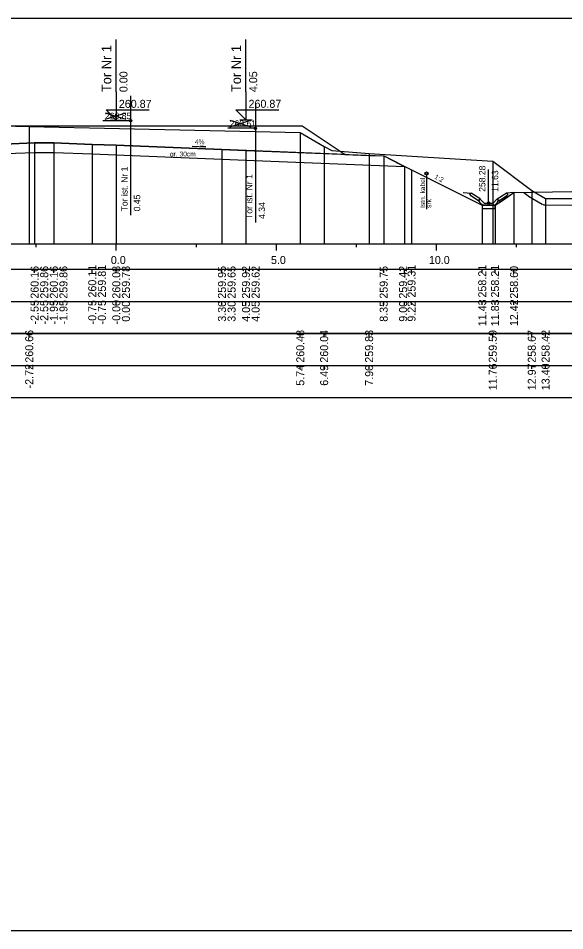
# Model space of a CAD drawing. Extents: x 6516023 to 6560129, y 5513077 to 5529206.
# Drawn here: x 6517307.15 to 6517324.22, y 5514484.66 to 5514513.16 of the extents above; entities that cross this region are included whole.
import ezdxf

# ---------------------------------------------------------------- set-up
doc = ezdxf.new("R2010")
doc.units = 0
for name, color, linetype in [('IR_default', 7, 'Continuous'), ('TOR_PRZEK_P-kable', 7, 'Continuous'), ('TOR_PRZEK_P-komponent', 7, 'Continuous'), ('TOR_PRZEK_P-odwodnienie', 7, 'Continuous'), ('TOR_PRZEK_P-opisy', 7, 'Continuous'), ('TOR_PRZEK_P-tabelka istniejace', 7, 'Continuous'), ('TOR_PRZEK_P-tabelka projektowane', 7, 'Continuous'), ('TOR_PRZEK_P-teren istniejacy', 7, 'Continuous'), ('TOR_PRZEK_P-tory istniejace', 7, 'Continuous'), ('TOR_PRZEK_P-tory projektowane', 7, 'Continuous'), ('TOR_PRZEK_P-uklad odniesienia', 7, 'Continuous'), ('TOR_PRZEK_P-warstwa ochronna I', 7, 'Continuous'), ('TOR_PRZEK_P-warstwa ochronna II', 7, 'Continuous'), ('TOR_PS_T-skarpy projektowane', 7, 'Continuous'), ('TOR_RAMKI-ramka+tabelka 1', 7, 'Continuous')]:
    doc.layers.add(name, color=color, linetype=linetype)

msp = doc.modelspace()

# ---------------------------------------------------------------- linework, layer by layer
at = {"layer": 'IR_default'}
msp.add_lwpolyline([(6517306.097, 5514509.798), (6517307.463, 5514509.798), (6517308.073, 5514509.798), (6517308.463, 5514509.798), (6517310.597, 5514509.798), (6517311.963, 5514509.798), (6517312.298, 5514509.799), (6517312.513, 5514509.799), (6517314.647, 5514509.799), (6517316.013, 5514509.799), (6517316.834, 5514509.252), (6517317.359, 5514508.902), (6517318.093, 5514508.873), (6517318.563, 5514508.854), (6517319.093, 5514508.589), (6517319.433, 5514508.419), (6517320.29, 5514507.99), (6517321.64, 5514507.315), (6517321.796, 5514507.315), (6517322.04, 5514507.315), (6517322.269, 5514507.467), (6517322.632, 5514507.71), (6517325.042, 5514507.758)], dxfattribs=at)
at = {"layer": 'TOR_PRZEK_P-kable'}
msp.add_line((6517319.901, 5514508.307), (6517319.901, 5514507.197), dxfattribs=at)
msp.add_circle((6517319.901, 5514508.307), 0.05, dxfattribs=at)
at = {"layer": 'TOR_PRZEK_P-komponent'}
msp.add_lwpolyline([(6517294.775, 5514509.735), (6517298.211, 5514509.865), (6517299.146, 5514509.242), (6517302.945, 5514509.118), (6517303.963, 5514509.797), (6517307.463, 5514509.798), (6517308.463, 5514509.798), (6517311.963, 5514509.798), (6517312.513, 5514509.799), (6517316.013, 5514509.799), (6517317.359, 5514508.902), (6517313.513, 5514509.056), (6517310.213, 5514509.188), (6517309.463, 5514509.218), (6517308.263, 5514509.266), (6517307.663, 5514509.266), (6517306.463, 5514509.218), (6517305.713, 5514509.188), (6517303.513, 5514509.1), (6517298.792, 5514509.253), (6517297.342, 5514509.195), (6517296.592, 5514509.165), (6517293.75, 5514509.052)], close=True, dxfattribs=at)
at = {"layer": 'TOR_PRZEK_P-odwodnienie'}
for p, q in [((6517321.84, 5514507.385), (6517321.84, 5514508.429)), ((6517321.531, 5514507.444), (6517321.27, 5514507.619)), ((6517321.576, 5514507.511), (6517321.295, 5514507.698)), ((6517321.533, 5514507.48), (6517321.58, 5514507.504)), ((6517321.576, 5514507.511), (6517321.568, 5514507.499)), ((6517321.7, 5514507.385), (6517321.58, 5514507.504)), ((6517321.98, 5514507.385), (6517322.1, 5514507.504)), ((6517322.1, 5514507.504), (6517322.148, 5514507.48)), ((6517322.105, 5514507.511), (6517322.385, 5514507.698)), ((6517322.105, 5514507.511), (6517322.113, 5514507.499)), ((6517322.149, 5514507.444), (6517322.411, 5514507.619)), ((6517321.543, 5514507.461), (6517321.531, 5514507.444)), ((6517321.65, 5514507.315), (6517322.03, 5514507.315)), ((6517321.7, 5514507.385), (6517321.98, 5514507.385)), ((6517322.138, 5514507.461), (6517322.149, 5514507.444))]:
    msp.add_line(p, q, dxfattribs=at)
for points in [[(6517321.049, 5514507.71), (6517321.295, 5514507.698)], [(6517321.245, 5514507.671), (6517321.295, 5514507.698)], [(6517321.245, 5514507.671), (6517321.27, 5514507.619)], [(6517321.568, 5514507.499), (6517321.532, 5514507.48)], [(6517321.532, 5514507.48), (6517321.543, 5514507.461)], [(6517321.58, 5514507.385), (6517321.533, 5514507.48)], [(6517322.1, 5514507.385), (6517322.148, 5514507.48)], [(6517322.113, 5514507.499), (6517322.149, 5514507.48)], [(6517322.149, 5514507.48), (6517322.138, 5514507.461)], [(6517322.632, 5514507.71), (6517322.385, 5514507.698)], [(6517322.436, 5514507.671), (6517322.385, 5514507.698)], [(6517322.436, 5514507.671), (6517322.411, 5514507.619)], [(6517321.65, 5514507.315), (6517321.58, 5514507.385)], [(6517321.64, 5514507.315), (6517321.64, 5514507.316), (6517321.64, 5514507.315), (6517321.64, 5514507.315), (6517321.64, 5514507.315), (6517321.641, 5514507.315), (6517321.64, 5514507.315), (6517321.641, 5514507.316)], [(6517321.641, 5514507.315), (6517321.64, 5514507.316), (6517321.641, 5514507.315), (6517321.64, 5514507.315), (6517321.641, 5514507.315), (6517321.641, 5514507.315), (6517321.641, 5514507.315), (6517321.641, 5514507.316)], [(6517322.04, 5514507.315), (6517321.64, 5514507.315), (6517321.64, 5514507.215), (6517322.04, 5514507.215), (6517322.04, 5514507.315)], [(6517322.03, 5514507.315), (6517322.1, 5514507.385)], [(6517322.04, 5514507.315), (6517322.04, 5514507.316), (6517322.04, 5514507.315), (6517322.04, 5514507.315), (6517322.04, 5514507.315), (6517322.041, 5514507.315), (6517322.04, 5514507.315), (6517322.041, 5514507.316)], [(6517322.04, 5514507.315), (6517322.04, 5514507.316), (6517322.04, 5514507.315), (6517322.04, 5514507.315), (6517322.04, 5514507.315), (6517322.041, 5514507.315), (6517322.04, 5514507.315), (6517322.041, 5514507.316)]]:
    msp.add_lwpolyline(points, dxfattribs=at)
msp.add_circle((6517321.84, 5514507.385), 0.035, dxfattribs=at)
at = {"layer": 'TOR_PRZEK_P-opisy'}
msp.add_lwpolyline([(6517312.588, 5514509.156), (6517313.006, 5514509.137), (6517312.838, 5514509.166)], dxfattribs=at)
at = {"layer": 'TOR_PRZEK_P-tabelka istniejace'}
for p, q in [((6517307.495, 5514503.206), (6517307.495, 5514503.306)), ((6517315.958, 5514503.206), (6517315.958, 5514503.306)), ((6517316.704, 5514503.206), (6517316.704, 5514503.306)), ((6517318.108, 5514503.206), (6517318.108, 5514503.306)), ((6517321.969, 5514503.206), (6517321.969, 5514503.306)), ((6517323.188, 5514503.206), (6517323.188, 5514503.306)), ((6517323.618, 5514503.206), (6517323.618, 5514503.306)), ((6517269.163, 5514502.306), (6517352.963, 5514502.306)), ((6517307.495, 5514502.206), (6517307.495, 5514502.306)), ((6517315.958, 5514502.206), (6517315.958, 5514502.306)), ((6517316.704, 5514502.206), (6517316.704, 5514502.306)), ((6517318.108, 5514502.206), (6517318.108, 5514502.306)), ((6517321.969, 5514502.206), (6517321.969, 5514502.306)), ((6517323.188, 5514502.206), (6517323.188, 5514502.306)), ((6517323.618, 5514502.206), (6517323.618, 5514502.306))]:
    msp.add_line(p, q, dxfattribs=at)
for points in [[(6517307.495, 5514509.771), (6517307.495, 5514506.306), (6517307.495, 5514506.176), (6517307.495, 5514506.106)], [(6517315.958, 5514509.589), (6517315.958, 5514506.306), (6517315.958, 5514506.176), (6517315.958, 5514506.106)], [(6517316.704, 5514509.149), (6517316.704, 5514506.306), (6517316.704, 5514506.176), (6517316.704, 5514506.106)], [(6517318.108, 5514508.933), (6517318.108, 5514506.306), (6517318.108, 5514506.176), (6517318.108, 5514506.106)], [(6517321.969, 5514508.694), (6517321.969, 5514506.306), (6517321.969, 5514506.176), (6517321.969, 5514506.106)], [(6517323.188, 5514507.776), (6517323.188, 5514506.306), (6517323.188, 5514506.176), (6517323.188, 5514506.106)], [(6517323.618, 5514507.525), (6517323.618, 5514506.306), (6517323.618, 5514506.176), (6517323.618, 5514506.106)]]:
    msp.add_lwpolyline(points, dxfattribs=at)
msp.add_lwpolyline([(6517269.163, 5514503.306), (6517269.163, 5514501.306), (6517352.963, 5514501.306), (6517352.963, 5514503.306)], close=True, dxfattribs=at)
at = {"layer": 'TOR_PRZEK_P-tabelka projektowane'}
for p, q in [((6517307.663, 5514505.206), (6517307.663, 5514505.306)), ((6517307.663, 5514505.206), (6517307.663, 5514505.306)), ((6517308.263, 5514505.206), (6517308.263, 5514505.306)), ((6517308.263, 5514505.206), (6517308.263, 5514505.306)), ((6517309.463, 5514505.206), (6517309.463, 5514505.306)), ((6517309.463, 5514505.206), (6517309.463, 5514505.306)), ((6517310.213, 5514505.206), (6517310.213, 5514505.306)), ((6517310.213, 5514505.206), (6517310.213, 5514505.306)), ((6517313.513, 5514505.206), (6517313.513, 5514505.306)), ((6517313.513, 5514505.206), (6517313.513, 5514505.306)), ((6517314.263, 5514505.206), (6517314.263, 5514505.306)), ((6517314.263, 5514505.206), (6517314.263, 5514505.306)), ((6517318.563, 5514505.206), (6517318.563, 5514505.306)), ((6517319.215, 5514505.206), (6517319.215, 5514505.306)), ((6517319.433, 5514505.206), (6517319.433, 5514505.306)), ((6517321.641, 5514505.206), (6517321.641, 5514505.306)), ((6517322.04, 5514505.206), (6517322.04, 5514505.306)), ((6517322.632, 5514505.206), (6517322.632, 5514505.306)), ((6517269.163, 5514504.306), (6517352.963, 5514504.306)), ((6517307.663, 5514504.206), (6517307.663, 5514504.306)), ((6517307.663, 5514504.206), (6517307.663, 5514504.306)), ((6517308.263, 5514504.206), (6517308.263, 5514504.306)), ((6517308.263, 5514504.206), (6517308.263, 5514504.306)), ((6517309.463, 5514504.206), (6517309.463, 5514504.306)), ((6517309.463, 5514504.206), (6517309.463, 5514504.306)), ((6517310.213, 5514504.206), (6517310.213, 5514504.306)), ((6517310.213, 5514504.206), (6517310.213, 5514504.306)), ((6517313.513, 5514504.206), (6517313.513, 5514504.306)), ((6517313.513, 5514504.206), (6517313.513, 5514504.306)), ((6517314.263, 5514504.206), (6517314.263, 5514504.306)), ((6517314.263, 5514504.206), (6517314.263, 5514504.306)), ((6517318.563, 5514504.206), (6517318.563, 5514504.306)), ((6517319.215, 5514504.206), (6517319.215, 5514504.306)), ((6517319.433, 5514504.206), (6517319.433, 5514504.306)), ((6517321.641, 5514504.206), (6517321.641, 5514504.306)), ((6517322.04, 5514504.206), (6517322.04, 5514504.306)), ((6517322.632, 5514504.206), (6517322.632, 5514504.306))]:
    msp.add_line(p, q, dxfattribs=at)
for points in [[(6517307.663, 5514509.266), (6517307.663, 5514506.306), (6517307.663, 5514506.176), (6517307.663, 5514506.106)], [(6517308.263, 5514509.266), (6517308.263, 5514506.306), (6517308.263, 5514506.176), (6517308.263, 5514506.106)], [(6517309.463, 5514509.218), (6517309.463, 5514506.306), (6517309.463, 5514506.176), (6517309.463, 5514506.106)], [(6517310.213, 5514509.188), (6517310.213, 5514506.306), (6517310.213, 5514506.176), (6517310.213, 5514506.106)], [(6517307.663, 5514508.966), (6517307.663, 5514506.306), (6517307.663, 5514506.176), (6517307.663, 5514506.106)], [(6517308.263, 5514508.966), (6517308.263, 5514506.306), (6517308.263, 5514506.176), (6517308.263, 5514506.106)], [(6517309.463, 5514508.918), (6517309.463, 5514506.306), (6517309.463, 5514506.176), (6517309.463, 5514506.106)], [(6517313.513, 5514509.056), (6517313.513, 5514506.306), (6517313.513, 5514506.176), (6517313.513, 5514506.106)], [(6517314.263, 5514509.026), (6517314.263, 5514506.306), (6517314.263, 5514506.176), (6517314.263, 5514506.106)], [(6517310.213, 5514508.888), (6517310.213, 5514506.306), (6517310.213, 5514506.176), (6517310.213, 5514506.106)], [(6517313.513, 5514508.756), (6517313.513, 5514506.306), (6517313.513, 5514506.176), (6517313.513, 5514506.106)], [(6517314.263, 5514508.726), (6517314.263, 5514506.306), (6517314.263, 5514506.176), (6517314.263, 5514506.106)], [(6517318.563, 5514508.854), (6517318.563, 5514506.306), (6517318.563, 5514506.176), (6517318.563, 5514506.106)], [(6517319.215, 5514508.528), (6517319.215, 5514506.306), (6517319.215, 5514506.176), (6517319.215, 5514506.106)], [(6517319.433, 5514508.419), (6517319.433, 5514506.306), (6517319.433, 5514506.176), (6517319.433, 5514506.106)], [(6517322.632, 5514507.71), (6517322.632, 5514506.306), (6517322.632, 5514506.176), (6517322.632, 5514506.106)], [(6517321.641, 5514507.315), (6517321.641, 5514506.306), (6517321.641, 5514506.176), (6517321.641, 5514506.106)], [(6517322.04, 5514507.315), (6517322.04, 5514506.306), (6517322.04, 5514506.176), (6517322.04, 5514506.106)]]:
    msp.add_lwpolyline(points, dxfattribs=at)
msp.add_lwpolyline([(6517269.163, 5514505.306), (6517269.163, 5514503.306), (6517352.963, 5514503.306), (6517352.963, 5514505.306)], close=True, dxfattribs=at)
at = {"layer": 'TOR_PRZEK_P-teren istniejacy'}
msp.add_lwpolyline([(6517304.934, 5514509.835), (6517307.495, 5514509.771), (6517315.958, 5514509.589), (6517316.704, 5514509.149), (6517316.94, 5514509.023), (6517318.108, 5514508.933), (6517321.969, 5514508.694), (6517323.188, 5514507.776), (6517323.618, 5514507.525), (6517324.539, 5514507.522)], dxfattribs=at)
at = {"layer": 'TOR_PRZEK_P-tory istniejace'}
for p, q in [((6517310.661, 5514510.731), (6517310.661, 5514507.011)), ((6517314.557, 5514510.494), (6517314.557, 5514506.774)), ((6517309.861, 5514510.003), (6517310.513, 5514510.206)), ((6517309.861, 5514510.206), (6517310.513, 5514510.003)), ((6517310.661, 5514509.956), (6517309.795, 5514509.956)), ((6517313.758, 5514509.766), (6517314.41, 5514509.969)), ((6517313.758, 5514509.969), (6517314.41, 5514509.766)), ((6517314.558, 5514509.719), (6517313.692, 5514509.719))]:
    msp.add_line(p, q, dxfattribs=at)
for centre in [(6517310.661, 5514509.956), (6517314.558, 5514509.719)]:
    msp.add_circle(centre, 0.035, dxfattribs=at)
at = {"layer": 'TOR_PRZEK_P-tory projektowane'}
for p, q in [((6517310.213, 5514510.856), (6517310.213, 5514512.488)), ((6517314.263, 5514510.857), (6517314.263, 5514512.489)), ((6517310.213, 5514510.856), (6517310.213, 5514509.978)), ((6517314.263, 5514510.857), (6517314.263, 5514509.979)), ((6517310.213, 5514509.978), (6517309.894, 5514510.297)), ((6517309.894, 5514510.297), (6517311.238, 5514510.297)), ((6517314.263, 5514509.979), (6517313.944, 5514510.298)), ((6517313.944, 5514510.298), (6517315.288, 5514510.298)), ((6517310.021, 5514509.978), (6517310.405, 5514509.978)), ((6517314.071, 5514509.979), (6517314.455, 5514509.979))]:
    msp.add_line(p, q, dxfattribs=at)
at = {"layer": 'TOR_PRZEK_P-uklad odniesienia'}
for p, q in [((6517272.963, 5514506.106), (6517352.963, 5514506.106)), ((6517307.713, 5514506.006), (6517307.713, 5514506.106)), ((6517310.213, 5514505.906), (6517310.213, 5514506.106)), ((6517312.713, 5514506.006), (6517312.713, 5514506.106)), ((6517315.213, 5514505.906), (6517315.213, 5514506.106)), ((6517317.713, 5514506.006), (6517317.713, 5514506.106)), ((6517320.213, 5514505.906), (6517320.213, 5514506.106)), ((6517322.713, 5514506.006), (6517322.713, 5514506.106))]:
    msp.add_line(p, q, dxfattribs=at)
at = {"layer": 'TOR_PRZEK_P-warstwa ochronna I'}
msp.add_lwpolyline([(6517303.864, 5514508.814), (6517305.713, 5514508.888), (6517306.463, 5514508.918), (6517307.663, 5514508.966), (6517308.263, 5514508.966), (6517309.463, 5514508.918), (6517310.213, 5514508.888), (6517313.513, 5514508.756), (6517314.263, 5514508.726), (6517319.215, 5514508.528)], dxfattribs=at)
at = {"layer": 'TOR_PRZEK_P-warstwa ochronna II'}
msp.add_lwpolyline([(6517306.463, 5514509.218), (6517307.663, 5514509.266), (6517308.263, 5514509.266), (6517309.463, 5514509.218), (6517310.213, 5514509.188), (6517313.513, 5514509.056), (6517314.263, 5514509.026), (6517318.563, 5514508.854), (6517319.433, 5514508.419), (6517321.641, 5514507.315), (6517322.04, 5514507.315), (6517322.632, 5514507.71), (6517325.042, 5514507.758)], dxfattribs=at)
at = {"layer": 'TOR_PS_T-skarpy projektowane'}
msp.add_line((6517323.087, 5514507.604), (6517323.517, 5514507.353), dxfattribs=at)
for points in [[(6517322.936, 5514507.716), (6517323.068, 5514507.616)], [(6517323.617, 5514507.325), (6517324.533, 5514507.322), (6517325.042, 5514507.291)]]:
    msp.add_lwpolyline(points, dxfattribs=at)
for centre, start, end in [((6517323.188, 5514507.776), 233.0304, 239.7392), ((6517323.618, 5514507.525), 239.7392, 269.7985)]:
    msp.add_arc(centre, 0.2, start, end, dxfattribs=at)
at = {"layer": 'TOR_RAMKI-ramka+tabelka 1'}
msp.add_lwpolyline([(6517179.513, 5514513.156), (6517427.013, 5514513.156), (6517427.013, 5514484.656), (6517179.513, 5514484.656)], close=True, dxfattribs=at)

# ---------------------------------------------------------------- texts
at = {"layer": 'TOR_PRZEK_P-kable'}
for s, height, p in [('Istn. kabel', 0.14999, (6517319.855, 5514507.233)), ('srk', 0.15, (6517320.05, 5514507.234))]:
    msp.add_text(s, height=height, rotation=90.0511, dxfattribs=at).set_placement(p)
at = {"layer": 'TOR_PRZEK_P-odwodnienie'}
for s, p in [('258.28', (6517321.74, 5514507.735)), ('11.63', (6517322.14, 5514507.735))]:
    msp.add_text(s, height=0.2, rotation=90, dxfattribs=at).set_placement(p)
at = {"layer": 'TOR_PRZEK_P-opisy'}
for s, rotation, p in [('4%', 359.8485, (6517312.667, 5514509.222)), ('1:2', 332.9299, (6517320.131, 5514508.157))]:
    msp.add_text(s, height=0.15, rotation=rotation, dxfattribs=at).set_placement(p)
at = {"layer": 'TOR_PRZEK_P-tabelka istniejace'}
for s, p in [('260.66', (6517307.62, 5514502.398)), ('260.48', (6517316.083, 5514502.398)), ('260.04', (6517316.829, 5514502.399)), ('259.83', (6517318.233, 5514502.398)), ('259.59', (6517322.094, 5514502.398)), ('258.67', (6517323.313, 5514502.398)), ('258.42', (6517323.743, 5514502.4)), ('-2.72', (6517307.62, 5514501.596)), ('11.76', (6517322.094, 5514501.538)), ('12.97', (6517323.313, 5514501.538)), ('13.40', (6517323.743, 5514501.538)), ('5.74', (6517316.083, 5514501.678)), ('6.49', (6517316.829, 5514501.678)), ('7.90', (6517318.233, 5514501.678))]:
    msp.add_text(s, height=0.25, rotation=90, dxfattribs=at).set_placement(p)
at = {"layer": 'TOR_PRZEK_P-tabelka projektowane'}
for s, p in [('260.16', (6517307.788, 5514504.398)), ('259.86', (6517308.088, 5514504.398)), ('260.16', (6517308.388, 5514504.398)), ('259.86', (6517308.688, 5514504.398)), ('260.11', (6517309.588, 5514504.433)), ('259.81', (6517309.888, 5514504.433)), ('260.08', (6517310.338, 5514504.398)), ('259.78', (6517310.638, 5514504.398)), ('259.95', (6517313.638, 5514504.397)), ('259.65', (6517313.938, 5514504.397)), ('259.92', (6517314.388, 5514504.4)), ('259.62', (6517314.688, 5514504.4)), ('259.75', (6517318.688, 5514504.397)), ('259.42', (6517319.293, 5514504.4)), ('259.31', (6517319.558, 5514504.433)), ('258.21', (6517321.766, 5514504.433)), ('258.21', (6517322.165, 5514504.433)), ('258.60', (6517322.757, 5514504.398)), ('-2.55', (6517307.788, 5514503.593)), ('-2.55', (6517308.088, 5514503.593)), ('-1.95', (6517308.388, 5514503.593)), ('-1.95', (6517308.688, 5514503.593)), ('-0.75', (6517309.588, 5514503.593)), ('-0.75', (6517309.888, 5514503.593)), ('-0.00', (6517310.338, 5514503.594)), ('11.43', (6517321.766, 5514503.538)), ('11.83', (6517322.165, 5514503.538)), ('12.42', (6517322.757, 5514503.54)), ('0.00', (6517310.638, 5514503.678)), ('3.30', (6517313.638, 5514503.678)), ('3.30', (6517313.938, 5514503.678)), ('4.05', (6517314.388, 5514503.677)), ('4.05', (6517314.688, 5514503.677)), ('8.35', (6517318.688, 5514503.677)), ('9.00', (6517319.293, 5514503.678)), ('9.22', (6517319.558, 5514503.68))]:
    msp.add_text(s, height=0.25, rotation=90, dxfattribs=at).set_placement(p)
at = {"layer": 'TOR_PRZEK_P-tory istniejace'}
for s, p in [('260.85', (6517309.861, 5514510.006)), ('260.61', (6517313.758, 5514509.769))]:
    msp.add_text(s, height=0.2, dxfattribs=at).set_placement(p)
for s, rotation, p in [('Tor ist. Nr 1', 90.0511, (6517310.567, 5514507.125)), ('Tor ist. Nr 1', 90.0511, (6517314.464, 5514506.888)), ('0.45', 90, (6517310.961, 5514507.126)), ('4.34', 90, (6517314.858, 5514506.889))]:
    msp.add_text(s, height=0.2, rotation=rotation, dxfattribs=at).set_placement(p)
at = {"layer": 'TOR_PRZEK_P-tory projektowane'}
for s, height, p in [('Tor Nr 1', 0.3, (6517310.058, 5514510.849)), ('Tor Nr 1', 0.3, (6517314.108, 5514510.851)), ('0.00', 0.25, (6517310.563, 5514510.848)), ('4.05', 0.25, (6517314.613, 5514510.849))]:
    msp.add_text(s, height=height, rotation=90, dxfattribs=at).set_placement(p)
for p in [(6517310.293, 5514510.358), (6517314.343, 5514510.359)]:
    msp.add_text('260.87', height=0.25, dxfattribs=at).set_placement(p)
at = {"layer": 'TOR_PRZEK_P-uklad odniesienia'}
for s, p in [('0.0', (6517310.044, 5514505.481)), ('5.0', (6517315.044, 5514505.481)), ('10.0', (6517319.974, 5514505.481))]:
    msp.add_text(s, height=0.25, dxfattribs=at).set_placement(p)
at = {"layer": 'TOR_PRZEK_P-warstwa ochronna I'}
msp.add_text('gr. 30cm', height=0.15, dxfattribs=at).set_placement((6517311.889, 5514508.84))

doc.saveas('drawing.dxf')
